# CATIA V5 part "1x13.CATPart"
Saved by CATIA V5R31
Part number: 1x13_cent
Definition: 13M Beam 4522937/41239
Nomenclature: 13M Beam 4522937/41239
Source: Unknown
Bounding box of the stored display mesh (mm): x -0.1 to 7.103, y -3.6 to 99.6, z 0 to 8
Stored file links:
  C:\Users\super\Desktop\LEGO\TFG-2621\TFG_02621_anejos\1x13.CATPart
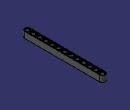
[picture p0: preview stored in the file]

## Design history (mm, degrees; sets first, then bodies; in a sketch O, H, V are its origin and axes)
AxisSystem1: origin (0, 0, 0), X (1, 0, 0), Y (0, 1, 0), Z (0, 0, 1)
Body1 "Body1" (main body)
  Solid1: solid without history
